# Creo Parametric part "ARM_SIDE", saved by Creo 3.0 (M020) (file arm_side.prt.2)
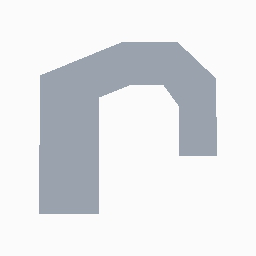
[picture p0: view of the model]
Units: millimeter Newton Second (mmNs); MM, TONNE, SECS

Created from: MMNS_PART_SOLID.PRT

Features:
  1. datum plane "RIGHT"
  2. datum plane "TOP"
  3. datum plane "FRONT"
  4. coordinate system
  5. sketch "Sketch 1"
  6. extrusion "Extrude 1"

Surfaces: 18 plane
